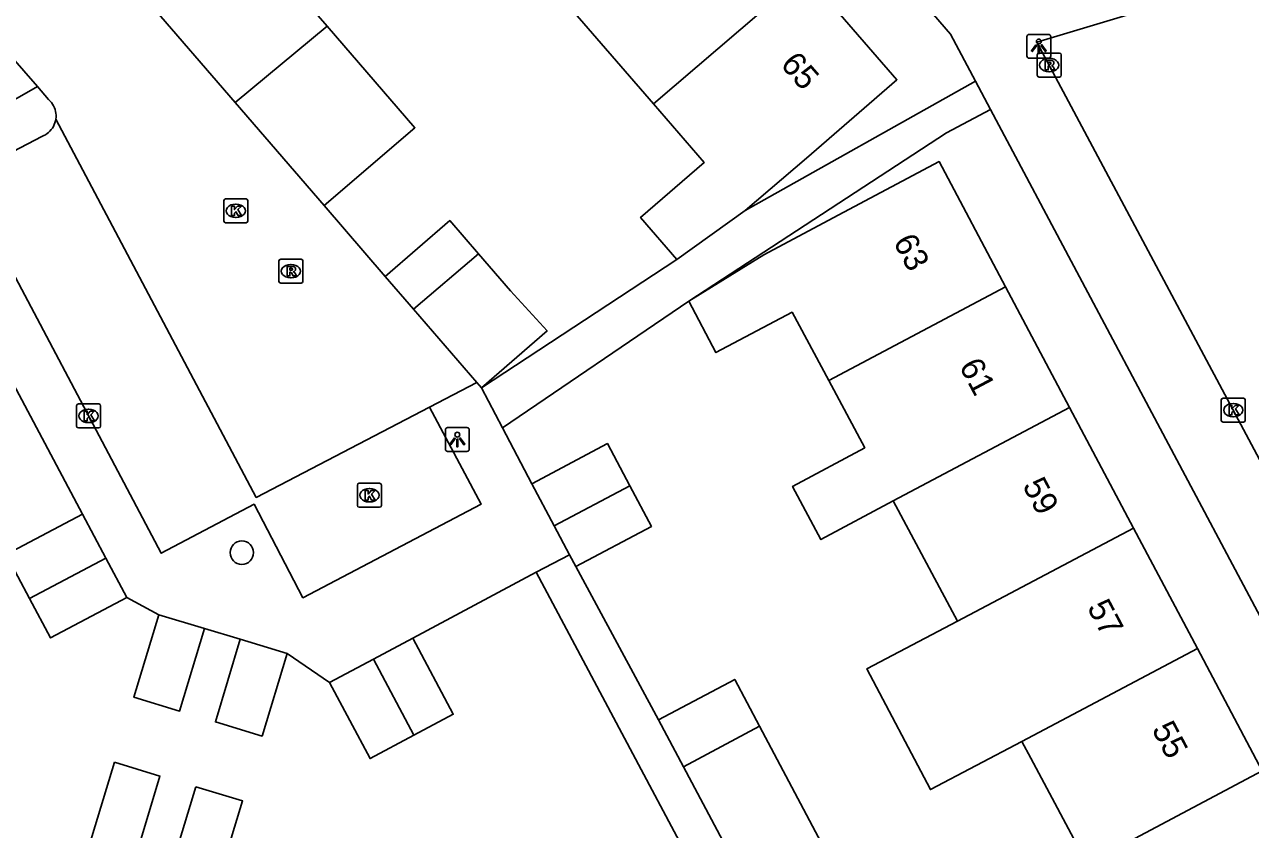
# Model space of a CAD drawing. Extents: x 160304 to 160954, y 383686 to 384161.
# Drawn here: x 160598.4 to 160649.6, y 383906 to 383939.6 of the extents above; entities that cross this region are included whole.
import ezdxf

# ---------------------------------------------------------------- set-up
doc = ezdxf.new("R2010")
doc.units = 0
for name, color, linetype in [('IMGEO_Boom', 7, 'Continuous'), ('IMGEO_Kolk', 7, 'Continuous'), ('IMGEO_Lichtpunt', 7, 'Continuous'), ('IMGEO_Pand', 7, 'Continuous'), ('IMGEO_Pand_nummerreeks', 7, 'Continuous'), ('IMGEO_Rijbaan_lokaal_open', 7, 'Continuous'), ('IMGEO_Rioolput', 7, 'Continuous'), ('IMGEO_Voetpad_open', 7, 'Continuous')]:
    doc.layers.add(name, color=color, linetype=linetype)

msp = doc.modelspace()

# ---------------------------------------------------------------- linework, layer by layer
at = {"layer": 'IMGEO_Boom'}
msp.add_circle((160607.442, 383917.514), 0.489, dxfattribs=at)
at = {"layer": 'IMGEO_Kolk'}
for p, q in [((160606.69, 383931.354), (160606.69, 383932.206)), ((160606.765, 383932.28), (160607.617, 383932.28)), ((160607.178, 383932.06), (160607.203, 383932.06)), ((160607.691, 383932.206), (160607.691, 383931.354)), ((160607.201, 383931.5), (160607.176, 383931.5)), ((160607.617, 383931.28), (160606.765, 383931.28)), ((160648.335, 383923.035), (160648.335, 383923.887)), ((160648.41, 383923.961), (160649.262, 383923.961)), ((160649.336, 383923.887), (160649.336, 383923.035)), ((160600.542, 383922.794), (160600.542, 383923.646)), ((160600.617, 383923.72), (160601.469, 383923.72)), ((160601.03, 383923.5), (160601.055, 383923.5)), ((160601.543, 383923.646), (160601.543, 383922.794)), ((160648.823, 383923.741), (160648.848, 383923.741)), ((160601.053, 383922.94), (160601.028, 383922.94)), ((160649.262, 383922.961), (160648.41, 383922.961)), ((160648.846, 383923.181), (160648.821, 383923.181)), ((160601.469, 383922.72), (160600.617, 383922.72)), ((160612.267, 383919.484), (160612.267, 383920.336)), ((160612.342, 383920.41), (160613.194, 383920.41)), ((160613.268, 383920.336), (160613.268, 383919.484)), ((160612.755, 383920.19), (160612.78, 383920.19)), ((160613.194, 383919.41), (160612.342, 383919.41)), ((160612.778, 383919.63), (160612.753, 383919.63))]:
    msp.add_line(p, q, dxfattribs=at)
for points in [[(160606.69, 383931.354), (160606.69, 383932.206)], [(160606.765, 383932.28), (160607.617, 383932.28)], [(160607.691, 383932.206), (160607.691, 383931.354)], [(160607.011, 383931.98), (160607.134, 383931.98), (160607.134, 383931.829), (160607.264, 383931.98), (160607.428, 383931.98), (160607.282, 383931.829), (160607.435, 383931.58), (160607.283, 383931.58), (160607.198, 383931.744), (160607.134, 383931.677), (160607.134, 383931.58), (160607.011, 383931.58), (160607.011, 383931.98)], [(160607.617, 383931.28), (160606.765, 383931.28)], [(160648.335, 383923.035), (160648.335, 383923.887)], [(160648.41, 383923.961), (160649.262, 383923.961)], [(160649.336, 383923.887), (160649.336, 383923.035)], [(160600.542, 383922.794), (160600.542, 383923.646)], [(160600.617, 383923.72), (160601.469, 383923.72)], [(160600.863, 383923.42), (160600.986, 383923.42), (160600.986, 383923.269), (160601.116, 383923.42), (160601.28, 383923.42), (160601.134, 383923.269), (160601.287, 383923.02), (160601.135, 383923.02), (160601.05, 383923.184), (160600.986, 383923.117), (160600.986, 383923.02), (160600.863, 383923.02), (160600.863, 383923.42)], [(160601.543, 383923.646), (160601.543, 383922.794)], [(160648.656, 383923.661), (160648.779, 383923.661), (160648.779, 383923.51), (160648.909, 383923.661), (160649.073, 383923.661), (160648.927, 383923.51), (160649.08, 383923.261), (160648.928, 383923.261), (160648.843, 383923.425), (160648.779, 383923.358), (160648.779, 383923.261), (160648.656, 383923.261), (160648.656, 383923.661)], [(160649.262, 383922.961), (160648.41, 383922.961)], [(160601.469, 383922.72), (160600.617, 383922.72)], [(160612.267, 383919.484), (160612.267, 383920.336)], [(160612.342, 383920.41), (160613.194, 383920.41)], [(160613.268, 383920.336), (160613.268, 383919.484)], [(160612.588, 383920.11), (160612.711, 383920.11), (160612.711, 383919.959), (160612.841, 383920.11), (160613.005, 383920.11), (160612.859, 383919.959), (160613.012, 383919.71), (160612.86, 383919.71), (160612.775, 383919.874), (160612.711, 383919.807), (160612.711, 383919.71), (160612.588, 383919.71), (160612.588, 383920.11)], [(160613.194, 383919.41), (160612.342, 383919.41)]]:
    msp.add_lwpolyline(points, dxfattribs=at)
for centre, start, end in [((160606.767, 383932.204), 91.552, 178.448), ((160606.767, 383932.204), 91.552, 178.448), ((160607.615, 383932.204), 1.552, 88.448), ((160607.615, 383932.204), 1.552, 88.448), ((160606.767, 383931.356), 181.552, 268.448), ((160606.767, 383931.356), 181.552, 268.448), ((160607.615, 383931.356), 271.552, 358.448), ((160607.615, 383931.356), 271.552, 358.448), ((160648.412, 383923.885), 91.552, 178.448), ((160648.412, 383923.885), 91.552, 178.448), ((160649.26, 383923.885), 1.552, 88.448), ((160649.26, 383923.885), 1.552, 88.448), ((160600.619, 383923.644), 91.552, 178.448), ((160600.619, 383923.644), 91.552, 178.448), ((160601.467, 383923.644), 1.552, 88.448), ((160601.467, 383923.644), 1.552, 88.448), ((160600.619, 383922.796), 181.552, 268.448), ((160600.619, 383922.796), 181.552, 268.448), ((160601.467, 383922.796), 271.552, 358.448), ((160601.467, 383922.796), 271.552, 358.448), ((160648.412, 383923.037), 181.552, 268.448), ((160648.412, 383923.037), 181.552, 268.448), ((160649.26, 383923.037), 271.552, 358.448), ((160649.26, 383923.037), 271.552, 358.448), ((160612.344, 383920.334), 91.552, 178.448), ((160612.344, 383920.334), 91.552, 178.448), ((160613.192, 383920.334), 1.552, 88.448), ((160613.192, 383920.334), 1.552, 88.448), ((160612.344, 383919.486), 181.552, 268.448), ((160612.344, 383919.486), 181.552, 268.448), ((160613.192, 383919.486), 271.552, 358.448), ((160613.192, 383919.486), 271.552, 358.448)]:
    msp.add_arc(centre, 0.0765, start, end, dxfattribs=at)
for centre, major_axis, ratio, start_param, end_param in [((160607.177, 383931.78), (-0.387, 0.002), 0.722429, 4.712389, 7.853982), ((160607.202, 383931.78), (-0.39, 0.002), 0.717154, 1.570796, 4.712389), ((160601.029, 383923.22), (-0.387, 0.002), 0.722429, 4.712389, 7.853982), ((160601.054, 383923.22), (-0.39, 0.002), 0.717154, 1.570796, 4.712389), ((160648.822, 383923.461), (-0.387, 0.002), 0.722429, 4.712389, 7.853982), ((160648.847, 383923.461), (-0.39, 0.002), 0.717154, 1.570796, 4.712389), ((160612.754, 383919.91), (-0.387, 0.002), 0.722429, 4.712389, 7.853982), ((160612.779, 383919.91), (-0.39, 0.002), 0.717154, 1.570796, 4.712389)]:
    msp.add_ellipse(centre, major_axis=major_axis, ratio=ratio, start_param=start_param, end_param=end_param, dxfattribs=at)
at = {"layer": 'IMGEO_Lichtpunt'}
for p, q in [((160640.218, 383939.05), (160640.218, 383938.243)), ((160640.218, 383939.05), (160640.218, 383938.243)), ((160641.12, 383939.145), (160640.312, 383939.145)), ((160641.12, 383939.145), (160640.312, 383939.145)), ((160641.214, 383938.243), (160641.214, 383939.05)), ((160641.214, 383938.243), (160641.214, 383939.05)), ((160640.312, 383938.149), (160641.12, 383938.149)), ((160640.312, 383938.149), (160641.12, 383938.149)), ((160615.94, 383922.64), (160615.94, 383921.833)), ((160615.94, 383922.64), (160615.94, 383921.833)), ((160616.842, 383922.735), (160616.034, 383922.735)), ((160616.842, 383922.735), (160616.034, 383922.735)), ((160616.936, 383921.833), (160616.936, 383922.64)), ((160616.936, 383921.833), (160616.936, 383922.64)), ((160616.034, 383921.739), (160616.842, 383921.739)), ((160616.034, 383921.739), (160616.842, 383921.739))]:
    msp.add_line(p, q, dxfattribs=at)
for points in [[(160640.592, 383938.714), (160640.631, 383938.686), (160640.443, 383938.424), (160640.405, 383938.451), (160640.592, 383938.714)], [(160640.694, 383938.666), (160640.741, 383938.666), (160640.741, 383938.344), (160640.694, 383938.344), (160640.694, 383938.666)], [(160640.804, 383938.686), (160640.842, 383938.713), (160641.029, 383938.451), (160640.99, 383938.423), (160640.804, 383938.686)], [(160616.314, 383922.304), (160616.353, 383922.276), (160616.165, 383922.014), (160616.127, 383922.041), (160616.314, 383922.304)], [(160616.526, 383922.276), (160616.564, 383922.303), (160616.751, 383922.041), (160616.712, 383922.013), (160616.526, 383922.276)], [(160616.416, 383922.256), (160616.463, 383922.256), (160616.463, 383921.934), (160616.416, 383921.934), (160616.416, 383922.256)]]:
    msp.add_lwpolyline(points, dxfattribs=at)
for centre in [(160640.717, 383938.848), (160616.439, 383922.438)]:
    msp.add_circle(centre, 0.0994, dxfattribs=at)
for centre, start, end in [((160640.312, 383939.05), 90, 180), ((160640.312, 383939.05), 90, 180), ((160641.12, 383939.05), 0, 90), ((160641.12, 383939.05), 0, 90), ((160640.312, 383938.243), 180, 270), ((160640.312, 383938.243), 180, 270), ((160641.12, 383938.243), 270, 0), ((160641.12, 383938.243), 270, 360), ((160616.034, 383922.64), 90, 180), ((160616.034, 383922.64), 90, 180), ((160616.842, 383922.64), 0, 90), ((160616.842, 383922.64), 0, 90), ((160616.034, 383921.833), 180, 270), ((160616.034, 383921.833), 180, 270), ((160616.842, 383921.833), 270, 0), ((160616.842, 383921.833), 270, 360)]:
    msp.add_arc(centre, 0.0946, start, end, dxfattribs=at)
at = {"layer": 'IMGEO_Pand'}
for points in [[(160607.365, 383943.686), (160611.004, 383939.482)], [(160630.965, 383941.666), (160624.623, 383936.239)], [(160628.454, 383931.789), (160631.011, 383933.975), (160634.791, 383937.247), (160630.965, 383941.666)], [(160607.169, 383936.294), (160603.531, 383940.497)], [(160624.623, 383936.239), (160620.895, 383940.542)], [(160607.169, 383936.294), (160611.004, 383939.482)], [(160611.004, 383939.482), (160614.67, 383935.248), (160610.873, 383932.006)], [(160610.873, 383932.006), (160607.169, 383936.294)], [(160625.61, 383929.75), (160624.093, 383931.504), (160626.741, 383933.794), (160624.623, 383936.239)], [(160639.33, 383928.604), (160636.553, 383933.837), (160632.137, 383931.494), (160629.242, 383929.947), (160626.098, 383928.007)], [(160625.61, 383929.75), (160628.454, 383931.789)], [(160613.427, 383929.036), (160616.125, 383931.371), (160617.321, 383929.99)], [(160617.321, 383929.99), (160614.61, 383927.67)], [(160617.321, 383929.99), (160618.66, 383928.443), (160620.183, 383926.765), (160617.446, 383924.395)], [(160614.61, 383927.67), (160613.427, 383929.036)], [(160631.946, 383924.697), (160639.33, 383928.604)], [(160642.001, 383923.569), (160639.33, 383928.604)], [(160626.098, 383928.007), (160627.237, 383925.861), (160630.417, 383927.55), (160631.946, 383924.697)], [(160617.252, 383924.619), (160614.61, 383927.67)], [(160617.446, 383924.395), (160617.252, 383924.619)], [(160631.946, 383924.697), (160633.449, 383921.891), (160630.435, 383920.276), (160631.621, 383918.062), (160634.635, 383919.676)], [(160642.001, 383923.569), (160634.635, 383919.676)], [(160644.671, 383918.537), (160642.001, 383923.569)], [(160619.545, 383920.393), (160622.703, 383922.068), (160623.64, 383920.302)], [(160620.48, 383918.63), (160619.545, 383920.393)], [(160620.48, 383918.63), (160623.64, 383920.302)], [(160623.64, 383920.302), (160624.54, 383918.606), (160621.382, 383916.931)], [(160634.635, 383919.676), (160637.323, 383914.66)], [(160598.584, 383915.595), (160597.607, 383917.431), (160600.784, 383919.123)], [(160600.784, 383919.123), (160601.762, 383917.287)], [(160621.118, 383917.428), (160620.48, 383918.63)], [(160637.323, 383914.66), (160644.671, 383918.537)], [(160647.339, 383913.508), (160644.671, 383918.537)], [(160601.762, 383917.287), (160598.584, 383915.595)], [(160601.762, 383917.287), (160602.636, 383915.645)], [(160621.382, 383916.931), (160621.118, 383917.428)], [(160602.636, 383915.645), (160599.458, 383913.953), (160598.584, 383915.595)], [(160605.884, 383914.348), (160604.843, 383910.902), (160602.938, 383911.477), (160603.979, 383914.923)], [(160603.979, 383914.923), (160605.884, 383914.348)], [(160637.323, 383914.66), (160633.533, 383912.66), (160636.191, 383907.623), (160640.012, 383909.64)], [(160609.33, 383913.307), (160608.289, 383909.861), (160606.337, 383910.451), (160607.377, 383913.897)], [(160607.377, 383913.897), (160609.33, 383913.307)], [(160612.934, 383913.074), (160614.576, 383913.948)], [(160614.576, 383913.948), (160616.267, 383910.769), (160614.627, 383909.896)], [(160611.107, 383912.102), (160612.934, 383913.074)], [(160612.934, 383913.074), (160614.627, 383909.896)], [(160640.012, 383909.64), (160647.339, 383913.508)], [(160640.012, 383909.64), (160640.385, 383908.944), (160642.729, 383904.527), (160650.045, 383908.409), (160647.339, 383913.508)], [(160614.627, 383909.896), (160612.798, 383908.923), (160611.107, 383912.102)], [(160629.058, 383910.27), (160628.02, 383912.225), (160624.842, 383910.538)], [(160624.842, 383910.538), (160625.88, 383908.582)], [(160629.058, 383910.27), (160625.88, 383908.582)], [(160631.757, 383905.183), (160629.058, 383910.27)], [(160602.12, 383908.768), (160604.025, 383908.193), (160602.987, 383904.756), (160601.082, 383905.331), (160602.12, 383908.768)], [(160625.88, 383908.582), (160628.579, 383903.496)], [(160605.518, 383907.742), (160607.471, 383907.152), (160606.433, 383903.715), (160604.48, 383904.305), (160605.518, 383907.742)]]:
    msp.add_lwpolyline(points, dxfattribs=at)
at = {"layer": 'IMGEO_Rijbaan_lokaal_open'}
for points in [[(160586.615, 383951.067), (160598.905, 383936.968)], [(160598.905, 383936.968), (160599.375, 383936.422), (160599.386, 383936.412), (160599.444, 383936.356), (160599.496, 383936.294), (160599.543, 383936.227), (160599.584, 383936.157), (160599.618, 383936.084), (160599.646, 383936.007), (160599.666, 383935.929), (160599.68, 383935.849), (160599.686, 383935.768), (160599.685, 383935.687), (160599.677, 383935.606)], [(160599.677, 383935.606), (160608.046, 383919.818), (160615.274, 383923.582)], [(160610.873, 383932.006), (160613.427, 383929.036)], [(160615.274, 383923.582), (160617.252, 383924.619)]]:
    msp.add_lwpolyline(points, dxfattribs=at)
at = {"layer": 'IMGEO_Rioolput'}
for p, q in [((160640.65, 383937.436), (160640.65, 383938.288)), ((160640.725, 383938.362), (160641.577, 383938.362)), ((160641.138, 383938.142), (160641.163, 383938.142)), ((160641.651, 383938.288), (160641.651, 383937.436)), ((160641.577, 383937.362), (160640.725, 383937.362)), ((160641.161, 383937.582), (160641.136, 383937.582)), ((160608.991, 383928.835), (160608.991, 383929.687)), ((160609.066, 383929.761), (160609.918, 383929.761)), ((160609.479, 383929.541), (160609.504, 383929.541)), ((160609.992, 383929.687), (160609.992, 383928.835)), ((160609.502, 383928.981), (160609.477, 383928.981)), ((160609.918, 383928.761), (160609.066, 383928.761))]:
    msp.add_line(p, q, dxfattribs=at)
for points in [[(160640.65, 383937.436), (160640.65, 383938.288)], [(160640.725, 383938.362), (160641.577, 383938.362)], [(160641.651, 383938.288), (160641.651, 383937.436)], [(160641.239, 383938.06), (160640.987, 383938.062), (160640.987, 383937.662)], [(160640.987, 383937.662), (160641.111, 383937.662), (160641.111, 383937.824), (160641.122, 383937.824)], [(160641.165, 383937.981), (160641.111, 383937.981), (160641.111, 383937.9)], [(160641.111, 383937.9), (160641.163, 383937.9)], [(160641.169, 383937.795), (160641.24, 383937.662), (160641.38, 383937.662), (160641.315, 383937.788)], [(160641.577, 383937.362), (160640.725, 383937.362)], [(160608.991, 383928.835), (160608.991, 383929.687)], [(160609.066, 383929.761), (160609.918, 383929.761)], [(160609.58, 383929.459), (160609.328, 383929.461), (160609.328, 383929.061)], [(160609.992, 383929.687), (160609.992, 383928.835)], [(160609.328, 383929.061), (160609.452, 383929.061), (160609.452, 383929.223), (160609.463, 383929.223)], [(160609.506, 383929.38), (160609.452, 383929.38), (160609.452, 383929.299)], [(160609.452, 383929.299), (160609.504, 383929.299)], [(160609.51, 383929.194), (160609.581, 383929.061), (160609.721, 383929.061), (160609.656, 383929.187)], [(160609.918, 383928.761), (160609.066, 383928.761)]]:
    msp.add_lwpolyline(points, dxfattribs=at)
for centre, radius, start, end in [((160640.727, 383938.286), 0.0765, 91.552, 178.448), ((160640.727, 383938.286), 0.0765, 91.552, 178.448), ((160641.575, 383938.286), 0.0765, 1.552, 88.448), ((160641.575, 383938.286), 0.0765, 1.552, 88.448), ((160641.121, 383937.771), 0.0533, 26.0293, 88.6989), ((160641.147, 383938.089), 0.19, 274.7715, 282.9687), ((160641.171, 383937.885), 0.0964, 77.0061, 93.1865), ((160641.185, 383937.942), 0.0378, 276.6634, 79.6772), ((160641.238, 383937.95), 0.109, 350.3612, 89.416), ((160641.236, 383937.95), 0.112, 277.5842, 350.9817), ((160641.22, 383937.735), 0.108, 29.5134, 73.7905), ((160640.727, 383937.438), 0.0765, 181.552, 268.448), ((160640.727, 383937.438), 0.0765, 181.552, 268.448), ((160641.575, 383937.438), 0.0765, 271.552, 358.448), ((160641.575, 383937.438), 0.0765, 271.552, 358.448), ((160609.068, 383929.685), 0.0765, 91.552, 178.448), ((160609.068, 383929.685), 0.0765, 91.552, 178.448), ((160609.579, 383929.349), 0.109, 350.3612, 89.416), ((160609.916, 383929.685), 0.0765, 1.552, 88.448), ((160609.916, 383929.685), 0.0765, 1.552, 88.448), ((160609.462, 383929.17), 0.0533, 26.0293, 88.6989), ((160609.488, 383929.488), 0.19, 274.7715, 282.9687), ((160609.512, 383929.284), 0.0964, 77.0061, 93.1865), ((160609.526, 383929.341), 0.0378, 276.6634, 79.6772), ((160609.577, 383929.349), 0.112, 277.5842, 350.9817), ((160609.561, 383929.134), 0.108, 29.5134, 73.7905), ((160609.068, 383928.837), 0.0765, 181.552, 268.448), ((160609.068, 383928.837), 0.0765, 181.552, 268.448), ((160609.916, 383928.837), 0.0765, 271.552, 358.448), ((160609.916, 383928.837), 0.0765, 271.552, 358.448)]:
    msp.add_arc(centre, radius, start, end, dxfattribs=at)
for centre, major_axis, ratio, start_param, end_param in [((160641.137, 383937.862), (-0.387, 0.002), 0.722429, 4.712389, 7.853982), ((160641.162, 383937.862), (-0.39, 0.002), 0.717154, 1.570796, 4.712389), ((160609.478, 383929.261), (-0.387, 0.002), 0.722429, 4.712389, 7.853982), ((160609.503, 383929.261), (-0.39, 0.002), 0.717154, 1.570796, 4.712389)]:
    msp.add_ellipse(centre, major_axis=major_axis, ratio=ratio, start_param=start_param, end_param=end_param, dxfattribs=at)
at = {"layer": 'IMGEO_Voetpad_open'}
for points in [[(160599.096, 383983.036), (160637.034, 383939.15), (160638.073, 383937.196)], [(160598.905, 383936.968), (160594.104, 383934.222), (160577.898, 383943.554)], [(160655.348, 383911.26), (160640.639, 383938.82), (160653.945, 383942.828)], [(160628.454, 383931.789), (160638.073, 383937.196)], [(160638.073, 383937.196), (160638.701, 383936.015)], [(160615.274, 383923.582), (160617.438, 383919.538), (160609.995, 383915.634), (160607.954, 383919.533), (160604.08, 383917.492), (160595.778, 383933.15), (160599.094, 383934.887), (160599.169, 383934.919), (160599.241, 383934.957), (160599.309, 383935.001), (160599.373, 383935.052), (160599.432, 383935.108), (160599.485, 383935.169), (160599.534, 383935.234), (160599.576, 383935.304), (160599.611, 383935.377), (160599.64, 383935.453), (160599.663, 383935.531), (160599.677, 383935.606)], [(160638.701, 383936.015), (160636.861, 383935.037), (160626.098, 383928.007)], [(160638.701, 383936.015), (160653.56, 383908.079)], [(160617.446, 383924.395), (160625.61, 383929.75)], [(160626.098, 383928.007), (160618.321, 383922.727)], [(160600.784, 383919.123), (160597.283, 383925.699)], [(160617.446, 383924.395), (160618.321, 383922.727)], [(160618.321, 383922.727), (160619.545, 383920.393)], [(160621.118, 383917.428), (160619.737, 383916.693)], [(160619.737, 383916.693), (160614.576, 383913.948)], [(160629.871, 383897.643), (160619.737, 383916.693)], [(160624.842, 383910.538), (160621.382, 383916.931)], [(160603.979, 383914.923), (160602.636, 383915.645)], [(160607.377, 383913.897), (160605.884, 383914.348)], [(160611.107, 383912.102), (160609.33, 383913.307)]]:
    msp.add_lwpolyline(points, dxfattribs=at)

# ---------------------------------------------------------------- texts
at = {"layer": 'IMGEO_Pand_nummerreeks'}
for s, rotation, p in [('65', 311.1799, (160629.892, 383937.866)), ('63', 297.9502, (160634.617, 383930.487)), ('61', 297.9502, (160637.369, 383925.301)), ('59', 297.9502, (160640.014, 383920.316)), ('57', 297.9487, (160642.713, 383915.23)), ('55', 297.9502, (160645.411, 383910.145))]:
    msp.add_text(s, height=1, rotation=rotation, dxfattribs=at).set_placement(p)

doc.saveas('drawing.dxf')
